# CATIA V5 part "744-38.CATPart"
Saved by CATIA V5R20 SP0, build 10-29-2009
Part number: 744-38
Revision: TUTTO
Definition: NON CONOSCIUTO
Nomenclature: 744-38
Source: Unknown
Bounding box of the stored display mesh (mm): x -33 to 33, y -33.5 to 32.819, z -37 to 45
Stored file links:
  C:\Users\Utente\Desktop\IO LAVORO\3D X SITO CF\X SITO\744\744-38.CATPart
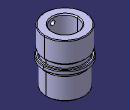
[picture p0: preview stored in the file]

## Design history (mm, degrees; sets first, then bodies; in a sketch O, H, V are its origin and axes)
Body1 "744-38 sol1" (main body)
  Solid1: solid without history
Body2 "IDV1M8_Ingrassatore-1"
  Solid2: solid without history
